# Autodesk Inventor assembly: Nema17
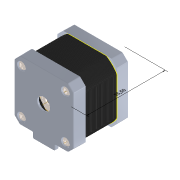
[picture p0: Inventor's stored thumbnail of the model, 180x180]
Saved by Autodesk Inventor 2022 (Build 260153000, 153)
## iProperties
Created: 2020-10
Part Number: Nema17
Document SubType Name: Assembly
Designer: admin
Sending System: SolidWorks 2020
Last Author: Simon
Last Saved: 2020-10-31
Author: admin
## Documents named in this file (11)
- C:\Users\admin\Desktop\disegno\disegno inventor thang\nema 17 motor\Nema17.iam
- C:\Users\admin\Desktop\disegno\disegno inventor thang\nema 17 motor\Bottom_cap.ipt
- C:\Users\admin\Desktop\disegno\disegno inventor thang\nema 17 motor\Protective_film_bottom.ipt
- C:\Users\admin\Desktop\disegno\disegno inventor thang\nema 17 motor\Bearing_spring.ipt
- C:\Users\admin\Desktop\disegno\disegno inventor thang\nema 17 motor\Bearing.ipt
- C:\Users\admin\Desktop\disegno\disegno inventor thang\nema 17 motor\Thick_washer.ipt
- C:\Users\admin\Desktop\disegno\disegno inventor thang\nema 17 motor\Rotor.ipt
- C:\Users\admin\Desktop\disegno\disegno inventor thang\nema 17 motor\Thick_washer_Thick.ipt
- C:\Users\admin\Desktop\disegno\disegno inventor thang\nema 17 motor\Stator.ipt
- C:\Users\admin\Desktop\disegno\disegno inventor thang\nema 17 motor\Top_cap.ipt
- C:\Users\admin\Desktop\disegno\disegno inventor thang\nema 17 motor\Screw.ipt
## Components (14 placed, 9 different names)
1. Bottom_cap:1
2. Protective_film_bottom:1
3. Bearing_spring:1
4. Bearing:1
5. Thick_washer:1
6. Rotor:1
7. Thick_washer:2
8. Bearing:2
9. Stator:1
10. Top_cap:1
11. Screw:1
12. Screw:2
13. Screw:3
14. Screw:4
